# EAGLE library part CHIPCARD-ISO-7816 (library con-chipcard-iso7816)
Chip card connector ISO 7816
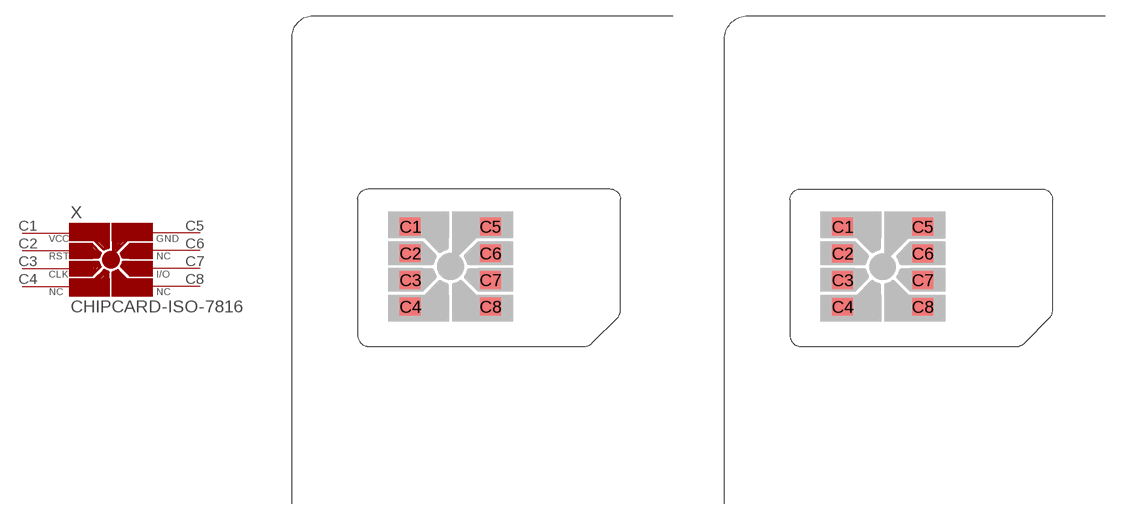
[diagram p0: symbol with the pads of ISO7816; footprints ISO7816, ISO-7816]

Designator prefix X

## CHIPCARD-ISO-7816 (OC_FARNELL: unknown; OC_NEWARK: unknown)  [ISO7816]
C1  VCC  pas
C2  RST  pas
C3  CLK  pas
C4  NC  pas
C5  GND  pas
C6  NC  pas
C7  I/O  pas
C8  NC  pas

## CHIPCARD-ISO-7816ISO (OC_FARNELL: unknown; OC_NEWARK: unknown)  [ISO-7816]
Pads as for ISO7816

## CHIPCARD-ISO-7816ANFOR (OC_FARNELL: unknown; OC_NEWARK: unknown)  [AFNOR-CHIPCARD]
Pads as for ISO7816

## Footprint ISO7816 (pad centres in mm)
ISO 7816 Chipcard
smd 2 x 1.7: C1 4.999,-3.599; C2 4.999,-6.138; C3 4.999,-8.683; C4 4.999,-11.222; C5 12.622,-3.6; C6 12.622,-6.14; C7 12.622,-8.68; C8 12.622,-11.222

## Footprint ISO-7816 (pad centres in mm)
ISO7816-1 Standard Chip Card Source: http://www.didya.com/iso-7816.asp
smd 2 x 1.7: C1 11.249,-20.099; C2 11.249,-22.638; C3 11.249,-25.183; C4 11.249,-27.722; C5 18.872,-20.1; C6 18.872,-22.64; C7 18.872,-25.18; C8 18.872,-27.722

## Footprint AFNOR-CHIPCARD (pad centres in mm)
AFNOR Chip Card Source: http://www.didya.com/iso-7816.asp
smd 2 x 1.7: C1 18.872,-17.541; C2 18.871,-15; C3 18.868,-12.457; C4 18.871,-9.92; C5 11.251,-17.542; C6 11.252,-15; C7 11.25,-12.459; C8 11.252,-9.92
